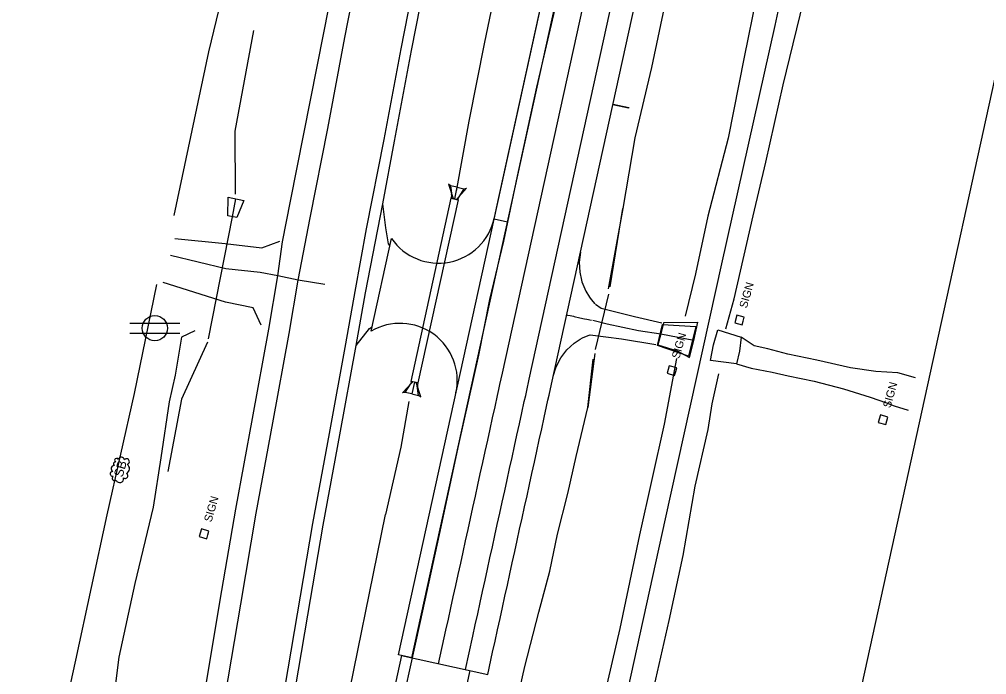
# Model space of a CAD drawing. Extents: x 14105231 to 14123593, y 8636972 to 8671693.
# Drawn here: x 14107915.8 to 14108338.7, y 8640392.2 to 8640678.7 of the extents above; entities that cross this region are included whole.
import ezdxf

# ---------------------------------------------------------------- set-up
doc = ezdxf.new("R2010")
doc.units = 0
for name, color, linetype in [('dsn3DCenterLine', 7, 'Continuous'), ('dsn3DPavementTop', 7, 'Continuous'), ('dsn3DShoulderTop', 7, 'Continuous'), ('dsnCulvertStrucProp', 7, 'Continuous'), ('dsnEdgeGranular', 7, 'Continuous'), ('dsnEdgePavement', 7, 'Continuous'), ('dsnShoulderPaved', 7, 'Continuous'), ('dsnSubdrains', 7, 'Continuous'), ('PhoDrainageArrow', 7, 'Continuous'), ('PhoEdgeEntrancePaved', 7, 'Continuous'), ('PhoEdgeEntranceUnpaved', 7, 'Continuous'), ('PhoEdgeRoadPaved', 7, 'Continuous'), ('PhoEdgeShoulderPaved', 7, 'Continuous'), ('PhoEdgeShoulderUnpaved', 7, 'Continuous'), ('PhoFence', 7, 'Continuous'), ('PhoRailRoadTrack', 7, 'Continuous'), ('PhoRoadPoints', 7, 'Continuous'), ('PhoVegetation', 7, 'Continuous'), ('SurCulvert', 7, 'Continuous'), ('SurDrainageArrowDown', 7, 'Continuous'), ('SurDrainageArrowUp', 7, 'Continuous'), ('SurEdgeEntrancePaved', 7, 'Continuous'), ('SurEdgeEntranceUnpaved', 7, 'Continuous'), ('SurEntranceCL', 7, 'Continuous'), ('SurUtilityPoleCell', 7, 'Continuous')]:
    doc.layers.add(name, color=color, linetype=linetype)

msp = doc.modelspace()

# ---------------------------------------------------------------- linework, layer by layer
at = {"layer": 'dsn3DCenterLine'}
for points in [[(14108099.08, 8640397.01), (14108102.3, 8640411.66), (14108103.37, 8640416.55), (14108104.44, 8640421.43), (14108105.51, 8640426.31), (14108106.59, 8640431.2), (14108107.66, 8640436.08), (14108108.73, 8640440.96), (14108109.8, 8640445.85), (14108110.88, 8640450.73), (14108111.95, 8640455.62), (14108113.02, 8640460.5), (14108114.1, 8640465.38), (14108115.17, 8640470.27), (14108116.24, 8640475.15), (14108117.31, 8640480.03), (14108118.39, 8640484.92), (14108119.46, 8640489.8), (14108120.53, 8640494.68), (14108121.61, 8640499.57), (14108122.68, 8640504.45), (14108123.75, 8640509.33), (14108124.82, 8640514.22), (14108125.42, 8640516.92), (14108125.9, 8640519.1), (14108126.97, 8640523.99), (14108234.25, 8641012.34)], [(14108155.11, 8640549.54), (14108155.48, 8640549.46), (14108156.58, 8640549.22), (14108158.04, 8640548.9), (14108158.38, 8640548.83), (14108160.82, 8640548.29), (14108162.92, 8640547.83), (14108163.83, 8640547.63), (14108165.85, 8640547.18)]]:
    msp.add_lwpolyline(points, dxfattribs=at)
at = {"layer": 'dsn3DPavementTop'}
for points in [[(14108087.36, 8640399.59), (14108222.53, 8641014.92)], [(14108110.8, 8640394.44), (14108114.02, 8640409.09), (14108115.09, 8640413.97), (14108116.16, 8640418.86), (14108117.23, 8640423.74), (14108118.31, 8640428.62), (14108119.38, 8640433.51), (14108120.45, 8640438.39), (14108121.53, 8640443.27), (14108122.6, 8640448.16), (14108123.67, 8640453.04), (14108124.74, 8640457.92), (14108125.82, 8640462.81), (14108126.89, 8640467.69), (14108127.96, 8640472.57), (14108129.03, 8640477.46), (14108130.11, 8640482.34), (14108131.18, 8640487.23), (14108132.25, 8640492.11), (14108133.33, 8640496.99), (14108134.4, 8640501.88), (14108135.47, 8640506.76), (14108136.54, 8640511.64), (14108137.14, 8640514.34), (14108137.62, 8640516.53), (14108138.69, 8640521.41), (14108245.97, 8641009.77)]]:
    msp.add_lwpolyline(points, dxfattribs=at)
at = {"layer": 'dsn3DShoulderTop'}
for points in [[(14108123.34, 8640591.33), (14108124.41, 8640596.22), (14108216.67, 8641016.2)], [(14108123.34, 8640591.33), (14108126.55, 8640605.98), (14108216.67, 8641016.2)], [(14108120.56, 8640392.29), (14108122.71, 8640402.06), (14108123.78, 8640406.94), (14108124.86, 8640411.83), (14108125.93, 8640416.71), (14108127, 8640421.59), (14108128.07, 8640426.48), (14108129.15, 8640431.36), (14108130.22, 8640436.24), (14108131.29, 8640441.13), (14108132.37, 8640446.01), (14108133.44, 8640450.9), (14108134.51, 8640455.78), (14108135.58, 8640460.66), (14108136.66, 8640465.55), (14108137.73, 8640470.43), (14108138.8, 8640475.31), (14108139.87, 8640480.2), (14108140.95, 8640485.08), (14108142.02, 8640489.96), (14108143.09, 8640494.85), (14108144.17, 8640499.73), (14108145.24, 8640504.61), (14108146.31, 8640509.5), (14108146.9, 8640512.2), (14108147.38, 8640514.38), (14108148.46, 8640519.27), (14108255.74, 8641007.62)], [(14108161.12, 8640576.89), (14108160.56, 8640572.57), (14108160.75, 8640568.22), (14108161.5, 8640564.65), (14108161.71, 8640563.96), (14108163.38, 8640559.94), (14108165, 8640557.27), (14108165.73, 8640556.27), (14108167.42, 8640554.3)], [(14108149.21, 8640522.68), (14108150.51, 8640526.84), (14108152.52, 8640530.71), (14108154.69, 8640533.64), (14108155.16, 8640534.18), (14108158.37, 8640537.13), (14108160.96, 8640538.87), (14108162.04, 8640539.47), (14108164.4, 8640540.55)]]:
    msp.add_lwpolyline(points, dxfattribs=at)
at = {"layer": 'dsnCulvertStrucProp'}
for p, q in [((14108104.3, 8640605.96), (14108103.34, 8640606.62)), ((14108103.34, 8640606.62), (14108105.38, 8640600.35)), ((14108107.23, 8640605.32), (14108104.3, 8640605.96)), ((14108104.3, 8640605.96), (14108104.92, 8640601.76)), ((14108106.11, 8640600.19), (14108107.23, 8640605.32)), ((14108107.23, 8640605.32), (14108110.16, 8640604.68)), ((14108104.64, 8640600.51), (14108104.83, 8640601.36)), ((14108111.31, 8640604.87), (14108106.84, 8640600.03)), ((14108110.16, 8640604.68), (14108107.85, 8640601.12)), ((14108110.16, 8640604.68), (14108111.31, 8640604.87)), ((14108106.11, 8640600.19), (14108104.64, 8640600.51)), ((14108104.64, 8640600.51), (14108107.57, 8640599.87)), ((14108106.11, 8640600.19), (14108105.38, 8640600.35)), ((14108106.11, 8640600.19), (14108107.57, 8640599.87)), ((14108106.11, 8640600.19), (14108106.84, 8640600.03)), ((14108107.57, 8640599.87), (14108107.76, 8640600.72)), ((14108083.35, 8640515.42), (14108087.82, 8640520.25)), ((14108084.5, 8640515.61), (14108086.81, 8640519.17)), ((14108087.09, 8640520.41), (14108086.9, 8640519.56)), ((14108088.55, 8640520.09), (14108087.09, 8640520.41)), ((14108090.02, 8640519.77), (14108087.09, 8640520.41)), ((14108088.55, 8640520.09), (14108087.43, 8640514.97)), ((14108088.55, 8640520.09), (14108087.82, 8640520.25)), ((14108088.55, 8640520.09), (14108090.02, 8640519.77)), ((14108088.55, 8640520.09), (14108089.28, 8640519.93)), ((14108091.32, 8640513.67), (14108089.28, 8640519.93)), ((14108090.36, 8640514.32), (14108089.74, 8640518.52)), ((14108090.02, 8640519.77), (14108089.83, 8640518.92)), ((14108084.5, 8640515.61), (14108083.35, 8640515.42)), ((14108087.43, 8640514.97), (14108084.5, 8640515.61)), ((14108087.43, 8640514.97), (14108090.36, 8640514.32)), ((14108090.36, 8640514.32), (14108091.32, 8640513.67))]:
    msp.add_line(p, q, dxfattribs=at)
msp.add_lwpolyline([(14108087.09, 8640520.41), (14108104.64, 8640600.51), (14108107.57, 8640599.87), (14108090.02, 8640519.77)], close=True, dxfattribs=at)
for centre, start, end in [((14108103.36, 8640601.69), 347.6362, 18.0276), ((14108109.23, 8640600.4), 137.2447, 167.6362), ((14108085.43, 8640519.88), 317.2447, 347.6362), ((14108091.29, 8640518.6), 167.6362, 198.0276)]:
    msp.add_arc(centre, 1.5, start, end, dxfattribs=at)
at = {"layer": 'dsnEdgeGranular'}
msp.add_line((14108069.58, 8640542.38), (14108078.48, 8640582.89), dxfattribs=at)
for centre, start, end in [((14108099.02, 8640597.15), 214.7666, 347.6102), ((14108082.25, 8640520.83), 347.6102, 120.4539)]:
    msp.add_arc(centre, 25, start, end, dxfattribs=at)
at = {"layer": 'dsnEdgePavement'}
msp.add_line((14108081.5, 8640400.87), (14108123.34, 8640591.33), dxfattribs=at)
at = {"layer": 'dsnShoulderPaved'}
for p, q in [((14108129.2, 8640590.05), (14108123.34, 8640591.33)), ((14108087.36, 8640399.59), (14108081.5, 8640400.87)), ((14108082.91, 8640400.56), (14108120.56, 8640392.29))]:
    msp.add_line(p, q, dxfattribs=at)
at = {"layer": 'dsnSubdrains'}
msp.add_lwpolyline([(14108175.28, 8640641.36), (14108175.35, 8640641.68), (14108182.19, 8640640.18), (14108182.11, 8640639.85)], close=True, dxfattribs=at)
at = {"layer": 'PhoDrainageArrow'}
for points in [[(14108278.23, 8641048.88), (14108269.34, 8641009.61), (14108262.19, 8640974.38), (14108255.59, 8640942.84), (14108248.55, 8640913.02), (14108244, 8640884.62), (14108236.43, 8640857.52), (14108225.07, 8640805.19), (14108217.47, 8640774.57), (14108210.02, 8640742.4), (14108203.42, 8640711.71), (14108198.23, 8640686.67), (14108192.15, 8640657.65), (14108184.81, 8640626.86), (14108179.61, 8640596.09), (14108173.2, 8640560.92)], [(14108119.26, 8640668.7), (14108129.95, 8640719.88), (14108147.91, 8640798.34), (14108161.76, 8640859.11)], [(14107992.5, 8640542.5), (14107986.71, 8640539.72), (14107983.97, 8640523.15), (14107981.33, 8640511.54), (14107977.61, 8640486.98), (14107974.35, 8640465.49), (14107966.29, 8640432.03), (14107959.23, 8640399.89), (14107954.58, 8640362.86), (14107950.26, 8640318.62), (14107941.92, 8640281.77), (14107932.54, 8640236.06), (14107927.16, 8640201.74)], [(14108131.15, 8640370.62), (14108136.75, 8640395.77), (14108142.92, 8640419.57), (14108147.76, 8640437.41), (14108151.1, 8640453.66), (14108155.63, 8640471.5), (14108159.21, 8640487.68), (14108164.35, 8640508.98), (14108166.66, 8640530.22)], [(14107981.25, 8639954.33), (14107990.5, 8640003.91), (14108002.9, 8640065.31), (14108014.76, 8640143.33), (14108023.07, 8640198.89), (14108037.44, 8640273.87), (14108056.81, 8640368.33), (14108075.83, 8640462.18)]]:
    msp.add_lwpolyline(points, dxfattribs=at)
at = {"layer": 'PhoEdgeEntrancePaved'}
for points in [[(14108208.28, 8640531.42), (14108194.79, 8640536.12), (14108196.91, 8640545.39), (14108211.49, 8640544.47)], [(14108221.11, 8640543.02), (14108231.38, 8640539.83), (14108230.55, 8640533.6), (14108229.35, 8640528.1), (14108217.96, 8640529.63), (14108219.27, 8640536.47)]]:
    msp.add_lwpolyline(points, close=True, dxfattribs=at)
at = {"layer": 'PhoEdgeEntranceUnpaved'}
for points in [[(14108077.82, 8640579.87), (14108077.14, 8640580.61), (14108076, 8640587.64), (14108074.76, 8640598.12)], [(14108062.99, 8640536.2), (14108068.93, 8640543.61), (14108069.99, 8640544.24)], [(14108307.61, 8640522.04), (14108299.83, 8640524.19), (14108290.24, 8640524.78), (14108279.17, 8640526.35), (14108264.48, 8640529.73), (14108251.81, 8640532.33), (14108243.01, 8640534.63), (14108237, 8640535.92), (14108231.38, 8640539.83)], [(14108229.35, 8640528.1), (14108235.79, 8640526.29), (14108244.86, 8640524.48), (14108251.96, 8640522.88), (14108263.22, 8640520.55), (14108276.02, 8640517.17), (14108287.7, 8640513.58), (14108294.88, 8640511.13), (14108298.23, 8640509.75), (14108304.41, 8640507.83)]]:
    msp.add_lwpolyline(points, dxfattribs=at)
at = {"layer": 'PhoEdgeRoadPaved'}
for points in [[(14108228.54, 8641043.39), (14108220.2, 8641004.55), (14108211.52, 8640965.11), (14108202.63, 8640925.97), (14108193.58, 8640884.18), (14108184.84, 8640844.87), (14108176.53, 8640805.92), (14108168.08, 8640767.14), (14108159.48, 8640726.63), (14108150.88, 8640687.84), (14108141.81, 8640649.05), (14108133.47, 8640610.14), (14108127.42, 8640581.81), (14108121.35, 8640556.22), (14108116.58, 8640531.9), (14108107.73, 8640492.91), (14108099.29, 8640453.48), (14108091.05, 8640415.44), (14108082.28, 8640375.85)], [(14108037.72, 8640564.73), (14108042.93, 8640591.98), (14108050.6, 8640631.07), (14108058.1, 8640670.74), (14108065.81, 8640710.28), (14108073.6, 8640748.26), (14108081.83, 8640788.19), (14108089.89, 8640827.35), (14108098.05, 8640866.55), (14108106.33, 8640905.55), (14108114.81, 8640945.75), (14108123.15, 8640985.27), (14108131.49, 8641024.51)], [(14108030.56, 8640378.39), (14108037.33, 8640418.75), (14108044.09, 8640458.29), (14108051.34, 8640497.72), (14108058.46, 8640536.87), (14108062.56, 8640559.77), (14108067.59, 8640587.2), (14108075.25, 8640626.23), (14108082.75, 8640665.91), (14108090.43, 8640705.28), (14108098.19, 8640743.14), (14108106.42, 8640783.06), (14108114.48, 8640822.19), (14108122.62, 8640861.32), (14108130.89, 8640900.3), (14108139.38, 8640940.52), (14108147.71, 8640980.01), (14108156.04, 8641019.17)], [(14107987.11, 8640269.68), (14107992.53, 8640303.44), (14107999.26, 8640343.53), (14108005.81, 8640382.69), (14108012.59, 8640423.08), (14108019.38, 8640462.8), (14108026.66, 8640502.35), (14108033.77, 8640541.45), (14108037.72, 8640564.73)], [(14108112.75, 8640394.01), (14108107.45, 8640370.1), (14108098.73, 8640330.92), (14108090.08, 8640291.99), (14108081.4, 8640254.48)]]:
    msp.add_lwpolyline(points, dxfattribs=at)
at = {"layer": 'PhoEdgeShoulderPaved'}
for points in [[(14108028.83, 8640566.6), (14108030.81, 8640581.42), (14108034.33, 8640599.23), (14108048.92, 8640672.78), (14108056.6, 8640712.22), (14108064.37, 8640750.65), (14108072.2, 8640790.7), (14108080.41, 8640829.47), (14108088.54, 8640868.57), (14108097.39, 8640907.56), (14108106.38, 8640947.53), (14108114.71, 8640987.05), (14108123.06, 8641026.31)], [(14108035.1, 8640377.84), (14108041.87, 8640418.18), (14108048.62, 8640457.65), (14108055.86, 8640497.03), (14108062.99, 8640536.2), (14108067.09, 8640559.1), (14108074.76, 8640598.12), (14108079.76, 8640625.45), (14108087.26, 8640665.14), (14108094.92, 8640704.44), (14108102.67, 8640742.25), (14108110.9, 8640782.17), (14108118.96, 8640821.29), (14108127.09, 8640860.39), (14108135.36, 8640899.36), (14108143.85, 8640939.58), (14108152.18, 8640979.07), (14108160.5, 8641018.19)], [(14107976.66, 8640261.83), (14107983.58, 8640305.16), (14107990.32, 8640345.26), (14107996.87, 8640384.41), (14108003.65, 8640424.82), (14108010.45, 8640464.61), (14108017.73, 8640504.2), (14108024.84, 8640543.28), (14108028.83, 8640566.6)], [(14108082.91, 8640400.56), (14108077.6, 8640376.62), (14108068.87, 8640337.38), (14108060.19, 8640298.33), (14108051.5, 8640258.92)]]:
    msp.add_lwpolyline(points, dxfattribs=at)
at = {"layer": 'PhoEdgeShoulderUnpaved'}
for points in [[(14108318.71, 8641051.69), (14108307.08, 8641002.33), (14108299.02, 8640961.93), (14108292.67, 8640933.25), (14108281.39, 8640886.36), (14108271.2, 8640841.64), (14108262.74, 8640800.86), (14108253.08, 8640759.61), (14108243.49, 8640715.43), (14108232.6, 8640662.26), (14108225.63, 8640626.79), (14108216.74, 8640592.65), (14108211.33, 8640567.43), (14108206.85, 8640549)], [(14108224.61, 8640543.45), (14108228.22, 8640556.56), (14108236.6, 8640592.89), (14108242.11, 8640616.24), (14108249.77, 8640650.12), (14108260.02, 8640692.6), (14108266.73, 8640728.06), (14108276.02, 8640770.55), (14108286.82, 8640814.3), (14108295.68, 8640855.24), (14108303.21, 8640890.82), (14108311.61, 8640929.16), (14108320.05, 8640968.63), (14108329.12, 8641008.72), (14108337.08, 8641046.47)], [(14108203.14, 8640530.45), (14108197.62, 8640501.72), (14108186.86, 8640453.37), (14108178.32, 8640412.34), (14108164.42, 8640352.86), (14108157.27, 8640320.43), (14108147.95, 8640280.22), (14108139.61, 8640238.22), (14108131.37, 8640197.44), (14108121.23, 8640154.1), (14108111.63, 8640113.53), (14108101.36, 8640061.12), (14108090.11, 8640014.84), (14108081.88, 8639973.52), (14108071.19, 8639923.35), (14108065.1, 8639894.33), (14108055.61, 8639851.07), (14108040.45, 8639783.16), (14108030.93, 8639738.65), (14108023.46, 8639705.86), (14108012.54, 8639655.12), (14108003.03, 8639616.7), (14107994.05, 8639575.4)], [(14108191.9, 8640380.58), (14108199.91, 8640415.95), (14108206, 8640444.36), (14108211.22, 8640474.69), (14108216.97, 8640499.48), (14108218.7, 8640510.66), (14108221.58, 8640523.71)]]:
    msp.add_lwpolyline(points, dxfattribs=at)
at = {"layer": 'PhoFence'}
for points in [[(14107983.54, 8640593.02), (14107998.65, 8640664.55), (14108004.16, 8640687.58), (14108015.03, 8640746.56), (14108029.31, 8640809.92), (14108039.43, 8640855.61)], [(14107655.12, 8639960.72), (14107705.91, 8639959.11), (14107788.6, 8639957.4), (14107842.57, 8639956.65), (14107856.07, 8640014.29), (14107883.63, 8640132.39), (14107890.73, 8640172.29), (14107901.76, 8640222.95), (14107923.56, 8640321.32), (14107940.51, 8640398.59), (14107954.25, 8640462.04), (14107966.16, 8640515.17), (14107975.96, 8640562.82)]]:
    msp.add_lwpolyline(points, dxfattribs=at)
at = {"layer": 'PhoRailRoadTrack'}
for points in [[(14108111.89, 8639603.32), (14108223.02, 8640108.8), (14108321.24, 8640556.85), (14108389.01, 8640865.95), (14108466.39, 8641217.04), (14108579.44, 8641730.84), (14108667.4, 8642132.59), (14108747.16, 8642495.71), (14108823.03, 8642839), (14108872.22, 8643064.53), (14108931.84, 8643335.45), (14108991.64, 8643609.03), (14109051.05, 8643877.56), (14109162.83, 8644387.73), (14109185, 8644489.59)], [(14108119.95, 8640104.52), (14108137.51, 8640184.4), (14108166.59, 8640316.33), (14108198.25, 8640460.33), (14108222.9, 8640571.84), (14108246.23, 8640676), (14108263.71, 8640757.87), (14108289.91, 8640876.29), (14108316.28, 8640996.71), (14108351.6, 8641156.22)]]:
    msp.add_lwpolyline(points, dxfattribs=at)
at = {"layer": 'PhoRoadPoints'}
for points in [[(14108232.27, 8640546.82), (14108232.27, 8640546.82), (14108232.73, 8640548.47), (14108229.43, 8640549.39), (14108228.51, 8640546.09), (14108231.81, 8640545.17), (14108232.27, 8640546.82)], [(14108202.73, 8640524.74), (14108202.73, 8640524.74), (14108203.19, 8640526.39), (14108199.89, 8640527.32), (14108198.96, 8640524.02), (14108202.26, 8640523.09), (14108202.73, 8640524.74)], [(14108295.04, 8640503.19), (14108295.04, 8640503.19), (14108295.5, 8640504.84), (14108292.2, 8640505.77), (14108291.27, 8640502.47), (14108294.57, 8640501.54), (14108295.04, 8640503.19)], [(14107998.17, 8640453.32), (14107998.17, 8640453.32), (14107998.65, 8640454.97), (14107995.36, 8640455.92), (14107994.41, 8640452.63), (14107997.7, 8640451.67), (14107998.17, 8640453.32)]]:
    msp.add_lwpolyline(points, dxfattribs=at)
at = {"layer": 'PhoVegetation'}
for centre, radius, start, end in [((14107958.34, 8640485.89), 0.9, 25.2768, 240.2946), ((14107960.42, 8640486.01), 1.3, 4.7871, 168.2519), ((14107957.35, 8640482.31), 1.41, 96.4869, 239.6668), ((14107957.68, 8640484.34), 0.794, 74.3437, 232.6671), ((14107962.69, 8640485.4), 1.21, 278.7126, 143.7703), ((14107961.66, 8640482.29), 2.27, 293.9015, 57.5809), ((14107956.54, 8640480.06), 1.04, 84.478, 288.2444), ((14107957.4, 8640478.12), 1.09, 119.2287, 310.6906), ((14107962.05, 8640479.16), 1.18, 230.909, 63.6435), ((14107959.68, 8640477.86), 1.67, 199.7121, 13.1681)]:
    msp.add_arc(centre, radius, start, end, dxfattribs=at)
at = {"layer": 'SurCulvert'}
msp.add_line((14108173.42, 8640558.55), (14108167.58, 8640534.44), dxfattribs=at)
msp.add_lwpolyline([(14107998.47, 8640539.1), (14108008.96, 8640592.42), (14108010.5, 8640600.27)], dxfattribs=at)
msp.add_lwpolyline([(14108007.07, 8640600.94), (14108013.93, 8640599.59), (14108010.92, 8640592.03), (14108006.99, 8640592.81)], close=True, dxfattribs=at)
at = {"layer": 'SurDrainageArrowDown'}
msp.add_line((14108167.42, 8640532.62), (14108164.35, 8640508.98), dxfattribs=at)
for points in [[(14108010.27, 8640602.27), (14108010.18, 8640629.91), (14108018.36, 8640673.93)], [(14108106.84, 8640603.62), (14108112.37, 8640634.27), (14108119.26, 8640668.7)], [(14107998.11, 8640537.54), (14107986.68, 8640512.71), (14107980.64, 8640481.12)], [(14108086.09, 8640511.72), (14108082.62, 8640491.76), (14108075.83, 8640462.18)]]:
    msp.add_lwpolyline(points, dxfattribs=at)
at = {"layer": 'SurDrainageArrowUp'}
msp.add_line((14108174.02, 8640561.77), (14108179.61, 8640596.09), dxfattribs=at)
at = {"layer": 'SurEdgeEntrancePaved'}
msp.add_lwpolyline([(14108212.45, 8640546.26), (14108197.34, 8640546.01), (14108196.25, 8640541.29), (14108194.96, 8640536.43), (14108203.43, 8640533.78), (14108208.79, 8640530.91), (14108210.67, 8640538.37), (14108212.46, 8640546.33)], dxfattribs=at)
at = {"layer": 'SurEdgeEntranceUnpaved'}
for points in [[(14107983.77, 8640582.96), (14108005.7, 8640580.69), (14108021.74, 8640578.81), (14108029.67, 8640581.74)], [(14108021.49, 8640544.99), (14108017.95, 8640552.63), (14108005.94, 8640555.11), (14107978.61, 8640563.64)], [(14108196.73, 8640545.92), (14108184.71, 8640548.65), (14108170.1, 8640552.3), (14108167.67, 8640554.01)], [(14108164.42, 8640540.57), (14108165.37, 8640540.8), (14108179.06, 8640539.12), (14108193.99, 8640536.56)]]:
    msp.add_lwpolyline(points, dxfattribs=at)
at = {"layer": 'SurEntranceCL'}
for points in [[(14108049.39, 8640562.78), (14108037.72, 8640564.73), (14108028.83, 8640566.6), (14108021.12, 8640568.04), (14108006.13, 8640569.62), (14107981.81, 8640575.48)], [(14108166.55, 8640547.22), (14108172.81, 8640545.65), (14108186.47, 8640542.76), (14108196.25, 8640541.29), (14108210.61, 8640538.41)]]:
    msp.add_lwpolyline(points, dxfattribs=at)
at = {"layer": 'SurUtilityPoleCell'}
for p, q in [((14107964.03, 8640545.91), (14107986.02, 8640545.91)), ((14107964.03, 8640541.51), (14107986.02, 8640541.51))]:
    msp.add_line(p, q, dxfattribs=at)
msp.add_circle((14107975.02, 8640543.71), 5.51, dxfattribs=at)

# ---------------------------------------------------------------- texts
at = {"layer": 'PhoRoadPoints'}
for rotation, p in [(74.2984, (14108233.82, 8640552.2)), (74.2984, (14108204.28, 8640530.13)), (74.2984, (14108296.59, 8640508.58)), (73.8832, (14107999.77, 8640458.7))]:
    msp.add_text('SIGN', height=3.499, rotation=rotation, dxfattribs=at).set_placement(p)
at = {"layer": 'PhoVegetation'}
msp.add_text('SB', height=3.999, rotation=73.8832, dxfattribs=at).set_placement((14107960.87, 8640478.27))

doc.saveas('drawing.dxf')
